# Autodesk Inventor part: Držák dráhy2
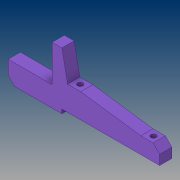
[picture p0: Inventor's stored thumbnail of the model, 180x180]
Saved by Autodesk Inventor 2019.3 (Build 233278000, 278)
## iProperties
Created: 2019-03
Part Number: Držák dráhy2
Material: Ocel, měkká, svařovaná
Document SubType Name: Modeling
Designer: B-hon
Density: 7.85 g/cm^3
Appearance: Fialová
Mass: 605.012 g
Surface Area: 186.842 cm^2
Volume: 77.0716 cm^3
Author: B-hon
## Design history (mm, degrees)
sketch "Náčrt1"
  geometry: L1 (0, 1)-(0, 45); L2 (0, 0)-(44, 0); L3 (0, 45)-(12, 45); L4 (12, 45)-(19, 10); L5 (-1, 0)-(-54, 0); L6 (-54, 0)-(-54, -25); L7 (132, -20)-(132, 0); L8 (117, -34.12)-(27, -34.12); L9 (19, 10)-(35, 10); L10 (35, 10)-(109, 0); L11 (109, 0)-(132, 0); L12 (-54, -25)-(12, -25); L13 (12, -25)-(12, -20); L14 (12, -20)-(132, -20); A1 r 1 centre (-1, 1) between (-1, 0) and (0, 1)
  constraints: 28 end point, 7 horizontal, 4 perpendicular, 2 point on circle, 2 point on line, 2 tangent, 1 centre point, 1 vertical
  dimensions: "d0" = 45 distance of L2.start L1.end; "d1" = 90 deg angle of L2 L1 (derived); "d5" = 132 distance from line of L7.end L1; "d6" = 54 distance of L2.start L5.end; "d7" = 25 distance of L5.end L6.end; "d8" = 90 distance of L8.start L8.end; "d9" = 15 distance from line of L7 L8.start; "d11" = 12 distance of L1.end L3.end; "d12" = 8 horizontal distance of L8.end L4.end; "d13" = 8 horizontal distance of L8.end L9.end; "d22" = 8 horizontal distance of L8.start L10.end; "d25" = 1 radius of A1; "d26" = 15 distance from line of L8.end L13
extrude "Vysunutí1" new body sketch "Náčrt1" distance "d14" = 15; taper "d15" = 0 deg
chamfer "Zkosení1" distance "d27" = 8; stored, may be unused: second distance "d28" = 2, angle "d29" = 45 deg
chamfer "Zkosení2" distance "d30" = 8; stored, may be unused: second distance "d31" = 2, angle "d32" = 45 deg
sketch "Náčrt3"
  geometry: L1 (0, 15)-(120, 15) reference; L2 (120, 0)-(120, 15) reference; 3 further points
  dimensions: "d33" = 7.5 distance from line of L1 point (15, 7.5); "d34" = 90 distance of point (105, 7.5) point (15, 7.5); "d35" = 15 distance from line of L2 point (105, 7.5); "d36" = 7.5 distance from line of L1 point (105, 7.5)
hole "Díra1" sketch "Náčrt3" at (15, 7.5), (105, 7.5) diameter "d37" = 6.5; stored, may be unused: countersink angle "d41" = 90 deg, drill point angle "d43" = 118 deg; dims "d38" = 6, "d39" = 4, "d40" = 2, "d42" = 8
node "Těleso1"
other parameters: "sa_0" = 0, "sa_1" = -1000000, "sa_2" = 0
